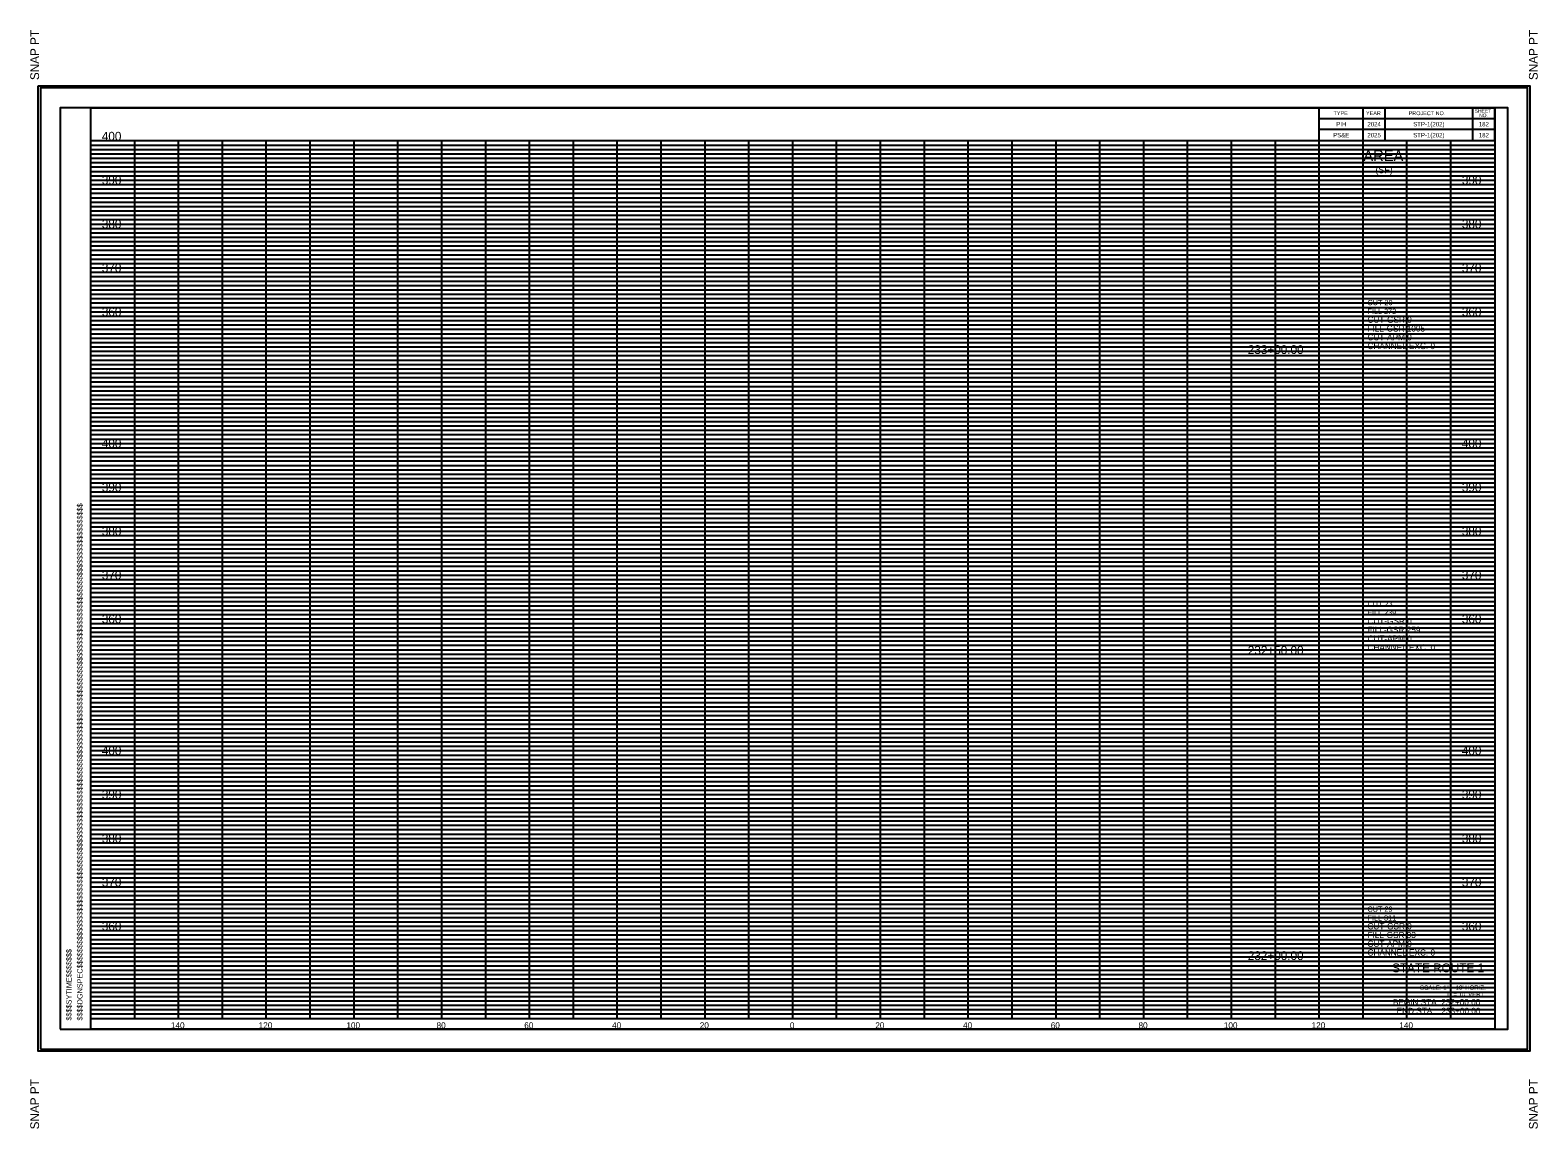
# Model space of a CAD drawing. Extents: x -200 to 23470, y -200 to 2389.
# Drawn here: x 9696.2 to 10039.8, y 1494.8 to 1745.2 of the extents above; entities that cross this region are included whole.
import ezdxf

# ---------------------------------------------------------------- set-up
doc = ezdxf.new("R2010")
doc.units = 0
for name, color, linetype in [('Default', 7, 'Continuous'), ('DESIGN - SCRATCH - User 1', 7, 'Continuous'), ('DESIGN - SHEET - Corner Text', 7, 'Continuous'), ('DESIGN - SHEET - Light Grid', 7, 'Continuous'), ('DESIGN - SHEET - Linework', 7, 'Continuous'), ('DESIGN - SHEET - Plot Shape', 7, 'Continuous'), ('DESIGN - TYPICAL - Text', 7, 'Continuous'), ('SURVEY - CENTERLINE - Preliminary', 7, 'Continuous')]:
    doc.layers.add(name, color=color, linetype=linetype)

# ---------------------------------------------------------------- blocks, each defined once
blk = doc.blocks.new('XSTSHT')
at = {"layer": 'DESIGN - SCRATCH - User 1'}
for p, q in [((28.5, 20.375), (28.5, 20.375)), ((29.25, 20.375), (29.25, 20.375)), ((30.5, 20.375), (30.5, 20.375)), ((31.75, 20.375), (31.75, 20.375)), ((28.5, 20.125), (28.5, 20.125)), ((29.25, 20.125), (29.25, 20.125)), ((30.5, 20.125), (30.5, 20.125)), ((31.75, 20.125), (31.75, 20.125)), ((0, 0), (0, 0))]:
    blk.add_line(p, q, dxfattribs=at)
at = {"layer": 'DESIGN - SHEET - Light Grid'}
for p, q in [((0, 19.9), (32, 19.9)), ((0, 19.8), (32, 19.8)), ((0, 19.7), (32, 19.7)), ((0, 19.6), (32, 19.6)), ((0, 19.5), (32, 19.5)), ((0, 19.4), (32, 19.4)), ((0, 19.3), (32, 19.3)), ((0, 19.2), (32, 19.2)), ((0, 19.1), (32, 19.1)), ((0, 18.9), (32, 18.9)), ((0, 18.8), (32, 18.8)), ((0, 18.7), (32, 18.7)), ((0, 18.6), (32, 18.6)), ((0, 18.5), (32, 18.5)), ((0, 18.4), (32, 18.4)), ((0, 18.3), (32, 18.3)), ((0, 18.2), (32, 18.2)), ((0, 18.1), (32, 18.1)), ((0, 17.9), (32, 17.9)), ((0, 17.8), (32, 17.8)), ((0, 17.7), (32, 17.7)), ((0, 17.6), (32, 17.6)), ((0, 17.5), (32, 17.5)), ((0, 17.4), (32, 17.4)), ((0, 17.3), (32, 17.3)), ((0, 17.2), (32, 17.2)), ((0, 17.1), (32, 17.1)), ((0, 16.9), (32, 16.9)), ((0, 16.8), (32, 16.8)), ((0, 16.7), (32, 16.7)), ((0, 16.6), (32, 16.6)), ((0, 16.5), (32, 16.5)), ((0, 16.4), (32, 16.4)), ((0, 16.3), (32, 16.3)), ((0, 16.2), (32, 16.2)), ((0, 16.1), (32, 16.1)), ((0, 15.9), (32, 15.9)), ((0, 15.8), (32, 15.8)), ((0, 15.7), (32, 15.7)), ((0, 15.6), (32, 15.6)), ((0, 15.5), (32, 15.5)), ((0, 15.4), (32, 15.4)), ((0, 15.3), (32, 15.3)), ((0, 15.2), (32, 15.2)), ((0, 15.1), (32, 15.1)), ((0, 14.9), (32, 14.9)), ((0, 14.8), (32, 14.8)), ((0, 14.7), (32, 14.7)), ((0, 14.6), (32, 14.6)), ((0, 14.5), (32, 14.5)), ((0, 14.4), (32, 14.4)), ((0, 14.3), (32, 14.3)), ((0, 14.2), (32, 14.2)), ((0, 14.1), (32, 14.1)), ((0, 13.9), (32, 13.9)), ((0, 13.8), (32, 13.8)), ((0, 13.7), (32, 13.7)), ((0, 13.6), (32, 13.6)), ((0, 13.5), (32, 13.5)), ((0, 13.4), (32, 13.4)), ((0, 13.3), (32, 13.3)), ((0, 13.2), (32, 13.2)), ((0, 13.1), (32, 13.1)), ((0, 12.9), (32, 12.9)), ((0, 12.8), (32, 12.8)), ((0, 12.7), (32, 12.7)), ((0, 12.6), (32, 12.6)), ((0, 12.5), (32, 12.5)), ((0, 12.4), (32, 12.4)), ((0, 12.3), (32, 12.3)), ((0, 12.2), (32, 12.2)), ((0, 12.1), (32, 12.1)), ((0, 11.9), (32, 11.9)), ((0, 11.8), (32, 11.8)), ((0, 11.7), (32, 11.7)), ((0, 11.6), (32, 11.6)), ((0, 11.5), (32, 11.5)), ((0, 11.4), (32, 11.4)), ((0, 11.3), (32, 11.3)), ((0, 11.2), (32, 11.2)), ((0, 11.1), (32, 11.1)), ((0, 10.9), (32, 10.9)), ((0, 10.8), (32, 10.8)), ((0, 10.7), (32, 10.7)), ((0, 10.6), (32, 10.6)), ((0, 10.5), (32, 10.5)), ((0, 10.4), (32, 10.4)), ((0, 10.3), (32, 10.3)), ((0, 10.2), (32, 10.2)), ((0, 10.1), (32, 10.1)), ((0, 9.9), (32, 9.9)), ((0, 9.8), (32, 9.8)), ((0, 9.7), (32, 9.7)), ((0, 9.6), (32, 9.6)), ((0, 9.5), (32, 9.5)), ((0, 9.4), (32, 9.4)), ((0, 9.3), (32, 9.3)), ((0, 9.2), (32, 9.2)), ((0, 9.1), (32, 9.1)), ((0, 8.9), (32, 8.9)), ((0, 8.8), (32, 8.8)), ((0, 8.7), (32, 8.7)), ((0, 8.6), (32, 8.6)), ((0, 8.5), (32, 8.5)), ((0, 8.4), (32, 8.4)), ((0, 8.3), (32, 8.3)), ((0, 8.2), (32, 8.2)), ((0, 8.1), (32, 8.1)), ((0, 7.9), (32, 7.9)), ((0, 7.8), (32, 7.8)), ((0, 7.7), (32, 7.7)), ((0, 7.6), (32, 7.6)), ((0, 7.5), (32, 7.5)), ((0, 7.4), (32, 7.4)), ((0, 7.3), (32, 7.3)), ((0, 7.2), (32, 7.2)), ((0, 7.1), (32, 7.1)), ((0, 6.9), (32, 6.9)), ((0, 6.8), (32, 6.8)), ((0, 6.7), (32, 6.7)), ((0, 6.6), (32, 6.6)), ((0, 6.5), (32, 6.5)), ((0, 6.4), (32, 6.4)), ((0, 6.3), (32, 6.3)), ((0, 6.2), (32, 6.2)), ((0, 6.1), (32, 6.1)), ((0, 5.9), (32, 5.9)), ((0, 5.8), (32, 5.8)), ((0, 5.7), (32, 5.7)), ((0, 5.6), (32, 5.6)), ((0, 5.5), (32, 5.5)), ((0, 5.4), (32, 5.4)), ((0, 5.3), (32, 5.3)), ((0, 5.2), (32, 5.2)), ((0, 5.1), (32, 5.1)), ((0, 4.9), (32, 4.9)), ((0, 4.8), (32, 4.8)), ((0, 4.7), (32, 4.7)), ((0, 4.6), (32, 4.6)), ((0, 4.5), (32, 4.5)), ((0, 4.4), (32, 4.4)), ((0, 4.3), (32, 4.3)), ((0, 4.2), (32, 4.2)), ((0, 4.1), (32, 4.1)), ((0, 3.9), (32, 3.9)), ((0, 3.8), (32, 3.8)), ((0, 3.7), (32, 3.7)), ((0, 3.6), (32, 3.6)), ((0, 3.5), (32, 3.5)), ((0, 3.4), (32, 3.4)), ((0, 3.3), (32, 3.3)), ((0, 3.2), (32, 3.2)), ((0, 3.1), (32, 3.1)), ((0, 2.9), (32, 2.9)), ((0, 2.8), (32, 2.8)), ((0, 2.7), (32, 2.7)), ((0, 2.6), (32, 2.6)), ((0, 2.5), (32, 2.5)), ((0, 2.4), (32, 2.4)), ((0, 2.3), (32, 2.3)), ((0, 2.2), (32, 2.2)), ((0, 2.1), (32, 2.1)), ((0, 1.9), (32, 1.9)), ((0, 1.8), (32, 1.8)), ((0, 1.7), (32, 1.7)), ((0, 1.6), (32, 1.6)), ((0, 1.5), (32, 1.5)), ((0, 1.4), (32, 1.4)), ((0, 1.3), (32, 1.3)), ((0, 1.2), (32, 1.2)), ((0, 1.1), (32, 1.1)), ((0, 0.9), (32, 0.9)), ((0, 0.8), (32, 0.8)), ((0, 0.7), (32, 0.7)), ((0, 0.6), (32, 0.6)), ((0, 0.5), (32, 0.5)), ((0, 0.4), (32, 0.4)), ((0, 0.3), (32, 0.3)), ((0, 0.2), (32, 0.2)), ((0, 0.1), (32, 0.1))]:
    blk.add_line(p, q, dxfattribs=at)
at = {"layer": 'DESIGN - SHEET - Linework'}
for p, q in [((32, 20.75), (28, 20.75)), ((28, 20), (28, 20.75)), ((29, 20), (29, 20.75)), ((29.5, 20), (29.5, 20.75)), ((31.5, 20), (31.5, 20.75)), ((32, 20), (32, 20.75)), ((32, 20.5), (28, 20.5)), ((0, 20), (32, 20)), ((1, 0), (1, 20)), ((2, 0), (2, 20)), ((3, 0), (3, 20)), ((4, 0), (4, 20)), ((5, 0), (5, 20)), ((6, 0), (6, 20)), ((7, 0), (7, 20)), ((8, 0), (8, 20)), ((9, 0), (9, 20)), ((10, 0), (10, 20)), ((11, 0), (11, 20)), ((12, 0), (12, 20)), ((13, 0), (13, 20)), ((14, 0), (14, 20)), ((15, 0), (15, 20)), ((16, 0), (16, 20)), ((17, 0), (17, 20)), ((18, 0), (18, 20)), ((19, 0), (19, 20)), ((20, 0), (20, 20)), ((21, 0), (21, 20)), ((22, 0), (22, 20)), ((23, 0), (23, 20)), ((24, 0), (24, 20)), ((25, 0), (25, 20)), ((26, 0), (26, 20)), ((27, 0), (27, 20)), ((32, 20.25), (28, 20.25)), ((28, 0), (28, 20)), ((29, 0), (29, 20)), ((30, 0), (30, 20)), ((31, 0), (31, 20)), ((0, 19), (32, 19)), ((0, 18), (32, 18)), ((0, 17), (32, 17)), ((0, 16), (32, 16)), ((0, 15), (32, 15)), ((0, 14), (32, 14)), ((0, 13), (32, 13)), ((0, 12), (32, 12)), ((0, 11), (32, 11)), ((0, 10), (32, 10)), ((0, 9), (32, 9)), ((0, 8), (32, 8)), ((0, 7), (32, 7)), ((0, 6), (32, 6)), ((0, 5), (32, 5)), ((0, 4), (32, 4)), ((0, 3), (32, 3)), ((0, 2), (32, 2)), ((0, 1), (32, 1)), ((0, 0), (32, 0))]:
    blk.add_line(p, q, dxfattribs=at)
for points in [[(-1.2, 21.25), (32.8, 21.25), (32.8, -0.75), (-1.2, -0.75)], [(0, 20.75), (32, 20.75), (32, -0.25), (0, -0.25)]]:
    blk.add_lwpolyline(points, close=True, dxfattribs=at)
at = {"layer": 'DESIGN - SHEET - Corner Text'}
for s, height, p in [('  SNAP PT', 0.2, (-1.18, 21.23)), ('  SNAP PT', 0.2, (32.98, 21.23)), ('$$$$DGNSPEC$$$$$$$$$$$$$$$$$$$$$$$$$$$$$$$$$$$$$$$$$$$$$$$$$$$$$$$$$$$$$$$$$$$$$$$$$$$$$$$$$$$$$$$$$$$$$$$$$$$$$$$$$$$$$$$$$$$', 0.12, (-0.19, -0.05)), ('$$$$SYTIME$$$$$$$', 0.12, (-0.44, -0.05)), ('SNAP PT  ', 0.2, (-1.18, -2.53)), ('SNAP PT  ', 0.2, (32.98, -2.53))]:
    blk.add_text(s, height=height, rotation=90, dxfattribs=at).set_placement(p)
at = {"layer": 'DESIGN - SHEET - Light Grid'}
for s, height, p in [('TYPE', 0.09, (28.326, 20.58)), ('YEAR', 0.09, (29.066, 20.58)), ('PROJECT NO.', 0.09, (30.038, 20.58)), ('SHEET', 0.08, (31.547, 20.635)), ('NO.', 0.08, (31.647, 20.535))]:
    blk.add_text(s, height=height, dxfattribs=at).set_placement(p)

msp = doc.modelspace()

# ---------------------------------------------------------------- linework, layer by layer
at = {"layer": 'DESIGN - SHEET - Plot Shape'}
for points in [[(9698.5, 1513), (10037.5, 1513), (10037.5, 1732), (9698.5, 1732)], [(9703, 1517.5), (10033, 1517.5), (10033, 1727.5), (9703, 1727.5)]]:
    msp.add_lwpolyline(points, close=True, dxfattribs=at)

# ---------------------------------------------------------------- block references
at = {"layer": 'DESIGN - SHEET - Plot Shape', "xscale": 10, "yscale": 10}
msp.add_blockref('XSTSHT', (9710, 1520), dxfattribs=at)
at = {"layer": 'SURVEY - CENTERLINE - Preliminary', "xscale": 10, "yscale": 10}
msp.add_blockref('XSTSHT', (9710, 1520), dxfattribs=at)
msp.add_blockref('XSTSHT', (9710, 1520), dxfattribs=at)

# ---------------------------------------------------------------- texts
at = {"layer": 'Default'}
for s, height, p in [('     400     ', 2, (9708.79, 1720)), ('     390     ', 2, (9708.79, 1710)), ('     390     ', 2, (10018.79, 1710)), ('     380     ', 2, (9708.79, 1700)), ('     380     ', 2, (10018.79, 1700)), ('     370     ', 2, (9708.79, 1690)), ('     370     ', 2, (10018.79, 1690)), ('     360     ', 2, (9708.79, 1680)), ('     360     ', 2, (10018.79, 1680)), ('     233+00.00     ', 2, (9970, 1671.38)), ('     400     ', 2, (9708.79, 1650)), ('     400     ', 2, (10018.79, 1650)), ('     390     ', 2, (9708.79, 1640)), ('     390     ', 2, (10018.79, 1640)), ('     380     ', 2, (9708.79, 1630)), ('     380     ', 2, (10018.79, 1630)), ('     370     ', 2, (9708.79, 1620)), ('     370     ', 2, (10018.79, 1620)), ('     360     ', 2, (9708.79, 1610)), ('     360     ', 2, (10018.79, 1610)), ('     232+50.00     ', 2, (9970, 1602.84)), ('     400     ', 2, (9708.79, 1580)), ('     400     ', 2, (10018.79, 1580)), ('     390     ', 2, (9708.79, 1570)), ('     390     ', 2, (10018.79, 1570)), ('     380     ', 2, (9708.79, 1560)), ('     380     ', 2, (10018.79, 1560)), ('     370     ', 2, (9708.79, 1550)), ('     370     ', 2, (10018.79, 1550)), ('     360     ', 2, (9708.79, 1540)), ('     360     ', 2, (10018.79, 1540)), ('     232+00.00     ', 2, (9970, 1533.29)), ('     140     ', 1.4, (9725.65, 1517.7)), ('     120     ', 1.4, (9745.65, 1517.7)), ('     100     ', 1.4, (9765.65, 1517.7)), ('     80     ', 1.4, (9786.2, 1517.7)), ('     60     ', 1.4, (9806.2, 1517.7)), ('     40     ', 1.4, (9826.2, 1517.7)), ('     20     ', 1.4, (9846.2, 1517.7)), ('     0     ', 1.4, (9866.74, 1517.7)), ('     0     ', 1.4, (9866.74, 1517.7)), ('     20     ', 1.4, (9886.2, 1517.7)), ('     40     ', 1.4, (9906.2, 1517.7)), ('     60     ', 1.4, (9926.2, 1517.7)), ('     80     ', 1.4, (9946.2, 1517.7)), ('     100     ', 1.4, (9965.65, 1517.7)), ('     120     ', 1.4, (9985.65, 1517.7)), ('     140     ', 1.4, (10005.65, 1517.7))]:
    msp.add_text(s, height=height, dxfattribs=at).set_placement(p)
at = {"layer": 'DESIGN - SHEET - Corner Text'}
for s, height, p in [('PS&E', 1, (9993.17, 1720.75)), ('PIH', 1, (9993.89, 1723.25)), ('2025', 1, (10000.97, 1720.75)), ('2024', 1, (10000.98, 1723.25)), ('STP-1(202)', 1, (10011.42, 1723.25)), ('STP-1(202)', 1, (10011.42, 1720.75)), ('182', 1, (10026.37, 1723.25)), ('182', 1, (10026.37, 1720.75)), ('STATE ROUTE 1', 2, (10006.62, 1530.5)), ('SCALE: 1" = 10\' HORIZ.', 1, (10012.96, 1526.5)), ('1" = 10\' VERT.', 1, (10018.93, 1525)), ('BEGIN STA. 232+00.00', 1.4, (10006.78, 1523)), ('END STA.   233+00.00', 1.4, (10007.65, 1521))]:
    msp.add_text(s, height=height, dxfattribs=at).set_placement(p)
at = {"layer": 'DESIGN - TYPICAL - Text'}
for s, height, p in [('AREA', 2.5, (10000.07, 1715.33)), ('(SF)', 1.5, (10002.83, 1712.58)), ('CUT 20', 1.2, (10001, 1682.49)), ('FILL 272', 1.2, (10001, 1680.49)), ('CUT-GSR 0', 1.4, (10001, 1678.49)), ('FILL-GSR 1005', 1.4, (10001, 1676.49)), ('CUT-APM 0', 1.4, (10001, 1674.49)), ('CHANNEL EXC. 0', 1.4, (10001, 1672.49)), ('CUT 23', 1.2, (10001, 1613.84)), ('FILL 239', 1.2, (10001, 1611.84)), ('CUT-GSR 0', 1.4, (10001, 1609.84)), ('FILL-GSR 259', 1.4, (10001, 1607.84)), ('CUT-APM 0', 1.4, (10001, 1605.84)), ('CHANNEL EXC. 0', 1.4, (10001, 1603.84)), ('CUT 29', 1.2, (10001, 1544.29)), ('FILL 311', 1.2, (10001, 1542.29)), ('CUT-GSR 0', 1.4, (10001, 1540.29)), ('FILL-GSR 93', 1.4, (10001, 1538.29)), ('CUT-APM 0', 1.4, (10001, 1536.29)), ('CHANNEL EXC. 0', 1.4, (10001, 1534.29))]:
    msp.add_text(s, height=height, dxfattribs=at).set_placement(p)

doc.saveas('drawing.dxf')
